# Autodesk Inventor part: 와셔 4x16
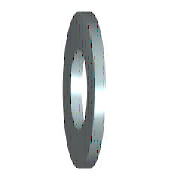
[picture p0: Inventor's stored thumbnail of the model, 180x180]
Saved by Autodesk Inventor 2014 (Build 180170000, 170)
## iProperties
IsCustomPart: 1
Created: 2012-02
Part Number: 와셔 4x16
Material: 강철, 연강
Description: 미터법 평면 와셔
Document SubType Name: Modeling
Standard: ANSI B18.22M
Designer: mduedu
Standard Revision: 1999
Standards Organization: ANSI
Language: ko-KR
Size Designation: 4 W
Categories: <MemberInstance><Categories><Category DisplayName="조임쇠" InternalName="e4da775c-781d-43d5-af7c-5136215cf5a6" Mnemonic="FSTN"><Category DisplayName="와셔" InternalN
Density: 1 g/cm^3
Appearance: 파란색 - 벽 페인트 - 광택
Author: mduedu
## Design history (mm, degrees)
sketch "스케치"
  geometry: C1 r 8 at (0, 0); C2 r 2.35 at (0, 0); 1 further point
  constraints: 2 centre point, 2 coincident
  dimensions: "d0" = 4.7 diameter of C2 (= SD1); "d1" = 16 diameter of C1 (= SD2)
extrude "본체" new body sketch "스케치" distance "d2" = 2.3 (= SD); taper "d3" = 0 deg
workaxis "Work Axis1"
workplane "Work Plane1"
body "Solid1"
other parameters: "SD1" = 4.7 [user parameter; used in 1 equation term], "SD2" = 16 [user parameter; used in 1 equation term], "SD" = 2.3 [user parameter; used in 1 equation term], "d4" = 0, "d5" = 0, "d6" = 0, "d7" = 0, "NND" = 4 [user parameter]
